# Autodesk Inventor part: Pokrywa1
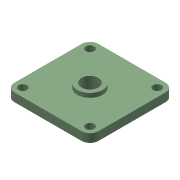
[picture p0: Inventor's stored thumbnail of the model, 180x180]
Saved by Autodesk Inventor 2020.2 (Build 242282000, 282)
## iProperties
Created: 2005-10
Part Number: Pokrywa1
Document SubType Name: Modeling
Designer: F.Stasiak
Stock Number: Pokrywa1
Density: 1 g/cm^3
Material: Ogólny
Appearance: Zielony pastelowy
Manager: www.cadconsulting.pl
Company: Fabian Stasiak CAD Consulting
Author: F.Stasiak
Subject: Zbiór ćwiczeń. Autodesk Inventor 2020. Kurs podstawowy
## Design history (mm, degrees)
sketch "Szkic1"
  geometry: L1 (0, 40)-(0, -40) reference; L2 (-10, 50)-(-90, 50) reference; L3 (-100, 40)-(-100, -40) reference; L4 (-90, -50)-(-10, -50) reference; C1 r 37.5 at (-50.839, -0.839) reference; C2 r 4 at (-90, -40) reference; C3 r 4 at (-10, 40) reference; C4 r 4 at (-10, -40) reference; C5 r 4 at (-90, 40) reference; A1 r 10 centre (-10, -40) between (-10, -50) and (0, -40) reference; A2 r 10 centre (-10, 40) between (0, 40) and (-10, 50) reference; A3 r 10 centre (-90, 40) between (-90, 50) and (-100, 40) reference; A4 r 10 centre (-90, -40) between (-100, -40) and (-90, -50) reference
  node "Odniesienie1"
extrude "Wyciągnięcie proste1" new body sketch "Szkic1" distance "d0" = 10; taper "d1" = 0 deg
hole "Otwór2" sketch "Szkic1" diameter "d12" = 10; stored, may be unused: countersink angle "d16" = 90 deg, drill point angle "d18" = 118 deg; dims "d13" = 6, "d14" = 4, "d15" = 2, "d17" = 8
sketch "Szkic3"
  geometry: L1 (-10, 40)-(-90, -40); C1 r 5 at (-10, 40) reference; C2 r 5 at (-90, -40) reference; C3 r 10 at (-50, 0)
  constraints: 2 end point, 1 centre point, 1 midpoint
  dimensions: "d19" = 20 diameter of C3
extrude "Wyciągnięcie proste3" cut sketch "Szkic3" extent not by distance; stored distance "d20" = 5; taper "d21" = 0 deg
sketch "Szkic4"
  geometry: C1 r 10 at (-50, 0) reference; C2 r 15 at (-50, 0)
  constraints: 1 centre point
  dimensions: "d22" = 30 diameter of C2
extrude "Wyciągnięcie proste4" join sketch "Szkic4" distance "d23" = 5; taper "d24" = 0 deg
node "Bryła1"
node "Korpusy bryłowe"
node "Korpusy powierzchniowe"
